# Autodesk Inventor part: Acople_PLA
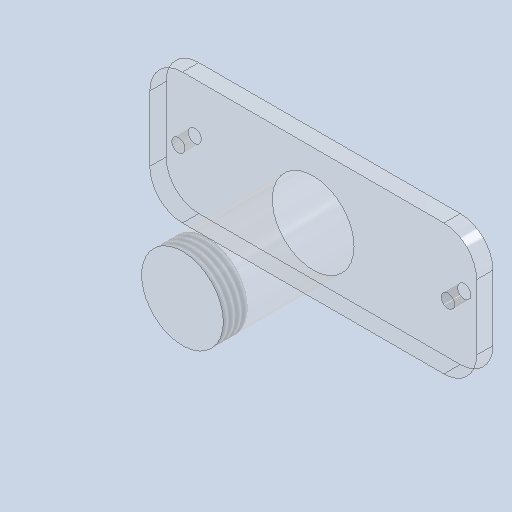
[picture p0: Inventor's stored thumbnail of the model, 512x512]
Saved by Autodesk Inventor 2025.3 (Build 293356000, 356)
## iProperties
Created: 2025-11
Part Number: Acople_PLA
Material: Plástico SAN
Document SubType Name: Modeling
Designer: Dell
Density: 1.068 g/cm^3
Appearance: Policarbonato - Claro
Mass: 333.846 g
Surface Area: 494.403 cm^2
Volume: 312.59 cm^3
Author: Dell
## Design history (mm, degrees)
sketch "Boceto1"
  geometry: L1 (-100, 40)-(100, 40); L2 (100, 40)-(100, -40); L3 (100, -40)-(-100, -40); L4 (-100, -40)-(-100, 40); L5 (-100, 40)-(100, -40); L6 (100, 40)-(-100, -40); C1 r 4.1 at (-82.5, 0); C2 r 4.1 at (82.5, 0); 1 further point
  constraints: 12 end point, 2 centre point, 2 midpoint, 2 parallel, 1 horizontal, 1 perpendicular
  dimensions: "d0" = 200 distance of L2.end L3.end; "d1" = 80 distance of L1.end L2.end
extrude "Extrusión1" new body sketch "Boceto1" distance "d5" = 10; taper "d6" = 0 deg
sketch "Boceto2"
  geometry: C1 r 25 at (0, 0); 1 further point
  constraints: 1 centre point, 1 coincident
  dimensions: "d7" = 50 diameter of C1
extrude "Extrusión2" join sketch "Boceto2" distance "d8" = 80; taper "d9" = 0 deg
feature "Rosca1" dims "d10" = 15, "d11" = 0
fillet "Empalme1" dims "d12" = 20
feature "Rosca2" dims "d13" = 80, "d14" = 0
feature "Rosca3" dims "d15" = 80, "d16" = 0
node "Sólido1"
